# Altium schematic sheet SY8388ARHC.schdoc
size 127 x 101 mm
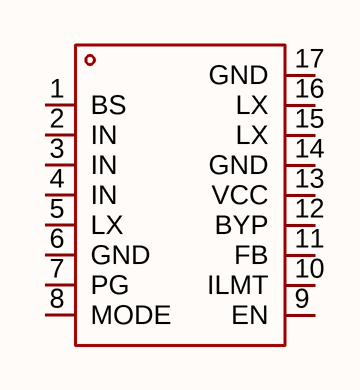
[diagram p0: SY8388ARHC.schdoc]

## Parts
U?  sy8388arhc  [QFN-16_L2.5-W2.5-P0.45-TL-EP0.6]  (value not drawn)

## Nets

Not connected (* = marked no-connect by the designer): U? 1(BS) 2(IN) 3(IN) 4(IN) 5(LX) 6(GND) 7(PG) 8(MODE) 9(EN) 10(ILMT) 11(FB) 12(BYP) 13(VCC) 14(GND) 15(LX) 16(LX) 17(GND)

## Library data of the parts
U? = sy8388arhc: 功能类型:降压型;工作电压:4V~24V;输出电压:-;输出电流:8A;输出类型:可调;; Manufacturer: Silergy(矽力杰); AddInBom: yes; ModelId: d6724371409549c497c9b62ea056431f; ModelTransform: 98.504,98.504,0,0,0,0,0,0,0; Function: 降压型; Voltage - Supply: 4V~24V; Output Current: 8A; Frequency - Switching: 510kHz~690kHz; Synchronous Rectifier: 是; Number of Outputs: 1; Topology: 降压式; Quiescent Current: 140uA; Switch tube (built-in/external): 内置; Output Type: 可调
